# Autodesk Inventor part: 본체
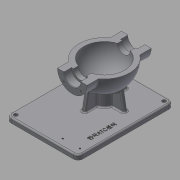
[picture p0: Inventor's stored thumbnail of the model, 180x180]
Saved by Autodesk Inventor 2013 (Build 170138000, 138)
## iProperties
Created: 2015-12
Part Number: 본체
Material: 알루미늄 6061
Document SubType Name: Modeling
Designer: mduedu
Density: 2.71 g/cm^3
Author: mduedu
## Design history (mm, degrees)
sketch "스케치1"
  geometry: L1 (-53, 0)-(53, 0); A1 r 53 centre (0, 0) between (53, 0) and (-53, 0); 2 further points
  constraints: 2 coincident, 2 end point, 2 point on circle, 1 centre point, 1 horizontal, 1 midpoint
  dimensions: "d0" = 53 radius of A1
revolve "회전1" sketch "스케치1" stored, may be unused: angle "d2" = 90 deg
feature "쉘1" dims "d11" = 10
node "작업 평면1"
sketch "스케치2"
  geometry: C1 r 31 at (0, 0); 1 further point
  constraints: 1 centre point, 1 coincident
  dimensions: "d4" = 62 diameter of C1
extrude "돌출1" join sketch "스케치2" stored distance "d5" = 10; taper "d6" = 0 deg
hole "구멍1" diameter "d14" = 35; stored, may be unused: countersink angle "d18" = 90 deg, drill point angle "d20" = 0 deg; dims "d12" = 10, "d13" = 10, "d15" = 6, "d16" = 4, "d17" = 2, "d19" = 16
hole "구멍2" diameter "d23" = 27; stored, may be unused: countersink angle "d27" = 90 deg, drill point angle "d29" = 0 deg; dims "d21" = 10, "d22" = 10, "d24" = 6, "d25" = 4, "d26" = 2, "d28" = 16
fillet "모깎기1" dims "d30" = 0.3
chamfer "모따기1" distance "d40" = 1; stored, may be unused: second distance "d41" = 2, angle "d42" = 45 deg
sketch "스케치4"
  geometry: L1 (0, 0)-(0, -25); L2 (0, 0)-(-17.678, -17.678); A1 r 25 centre (0, 0) between (-17.678, -17.678) and (0, -25); 1 further point
  constraints: 4 end point, 2 point on circle, 1 centre point, 1 coincident, 1 vertical
  dimensions: "d43" = 50 diameter of A1; "d47" = 45 deg angle of L1 L2
hole "구멍4" sketch "스케치4" at (-17.678, -17.678) diameter "d49" = 3.242; stored, may be unused: countersink angle "d53" = 90 deg, drill point angle "d55" = 118 deg; dims "d50" = 11, "d51" = 4, "d52" = 2, "d54" = 13
node "작업 평면3"
sketch "스케치6" dims "d22" = 10
  geometry: L1 (-70, -75)-(130, -75); L2 (130, -75)-(130, 75); L3 (130, 75)-(-70, 75); L4 (-70, 75)-(-70, -75); 2 further points
  constraints: 8 end point, 2 parallel, 1 coincident, 1 horizontal, 1 perpendicular
  dimensions: "d158" = 200 distance of L3.end L2.end; "d159" = 150 distance of L2.end L1.end; "d162" = 75 distance from line of L1 point (0, 0); "d163" = 70 distance from line of L4 point (0, 0)
extrude "돌출3" join sketch "스케치6" distance "d80" = 10; taper "d81" = 0 deg
sketch "스케치7"
  geometry: C1 r 20 at (0, 0); 2 further points
  constraints: 2 coincident, 1 centre point
  dimensions: "d82" = 40 diameter of C1
extrude "돌출4" join sketch "스케치7" stored distance "d84" = 10; taper "d85" = 0 deg
sketch "스케치8"
  geometry: 3 further points
  constraints: 2 coincident
hole "구멍6" sketch "스케치8" at (0, 0) diameter "d86" = 20; stored, may be unused: countersink angle "d90" = 90 deg, drill point angle "d92" = 118 deg; dims "d87" = 7, "d88" = 40, "d89" = 5, "d91" = 10
fillet "모깎기2" dims "d93" = 0.3
sketch "스케치9"
  geometry: L1 (-45, -75)-(-38.245, -36.692); L2 (70, -75)-(-130, -75) reference; A1 r 53 centre (0, 0) between (42.988, 31) and (42.988, -31) reference; 1 further point
  constraints: 2 end point, 1 coincident, 1 point on circle, 1 point on line
  dimensions: "d94" = 45 horizontal distance of L1.start point (0, 0); "d160" = 80 deg angle of L2 L1
feature "리브1" sketch "스케치9" dims "d96" = 1, "d97" = 8, "d98" = 0, "d99" = 0, "d100" = 1, "d101" = 1
fillet "모깎기3" dims "d120" = 3
fillet "모깎기4" dims "d121" = 3, "d122" = 3
fillet "모깎기5" dims "d123" = 3
sketch "스케치12"
  geometry: L1 (0, 100)-(0, -100); L2 (0, 100)-(100, 100); L3 (100, 100)-(100, -100); L4 (100, -100)-(0, -100); 2 further points
  constraints: 8 end point, 3 perpendicular, 1 coincident, 1 midpoint, 1 vertical
  dimensions: "d127" = 200 distance of L2.end L3.end; "d129" = 100 distance between parallel lines of L1 L3
extrude "돌출5" cut sketch "스케치12" stored distance "d130" = 10; taper "d131" = 0 deg
fillet "모깎기10" dims "d164" = 10
fillet "모깎기11" dims "d165" = 3
sketch "스케치15"
  geometry: C1 r 4 at (-120, 65); C2 r 4 at (60, 65); C3 r 4 at (60, -65); A1 r 10 centre (-120, 65) between (-120, 75) and (-130, 65) reference; A2 r 10 centre (60, 65) between (70, 65) and (60, 75) reference; A3 r 10 centre (60, -65) between (60, -75) and (70, -65) reference; 1 further point
  constraints: 3 centre point, 3 coincident, 2 equal radius
  dimensions: "d166" = 8 diameter of C1
extrude "돌출8" cut sketch "스케치15" stored distance "d167" = 10; taper "d168" = 0 deg
sketch "스케치16"
  geometry: L1 (-130, 65)-(-130, -65) reference; L2 (-120, -75)-(60, -75) reference; 2 further points
  constraints: 1 other
  dimensions: "d169" = 70 distance from line of point (-60, -55) L1; "d170" = 20 distance from line of point (-60, -55) L2
feature "엠보싱2" sketch "스케치16" dims "d171" = 0.5, "d172" = 0
sketch "스케치17"
  geometry: L1 (-120, 75)-(60, 75) reference; L2 (-130, -65)-(-130, 65) reference; 2 further points
  constraints: 1 vertical alignment
  dimensions: "d180" = 12 distance from line of L1 point (-114, 63); "d181" = 16 distance from line of point (-114, 63) L2; "d182" = 36 distance of point (-114, 27) point (-114, 63)
hole "구멍9" sketch "스케치17" at (-114, 63), (-114, 27) diameter "d173" = 3.242; stored, may be unused: countersink angle "d177" = 90 deg, drill point angle "d179" = 0 deg; dims "d174" = 6, "d175" = 4, "d176" = 2, "d178" = 8
node "솔리드1"
mirror "대칭1"
mirror "대칭2"
pattern_circular "원형 패턴1" dims angle "d57" = 360 deg
mirror "대칭3"
pattern_circular "원형 패턴3" dims angle "d103" = 360 deg
other parameters: "d3" = 67, "d77" = -85
